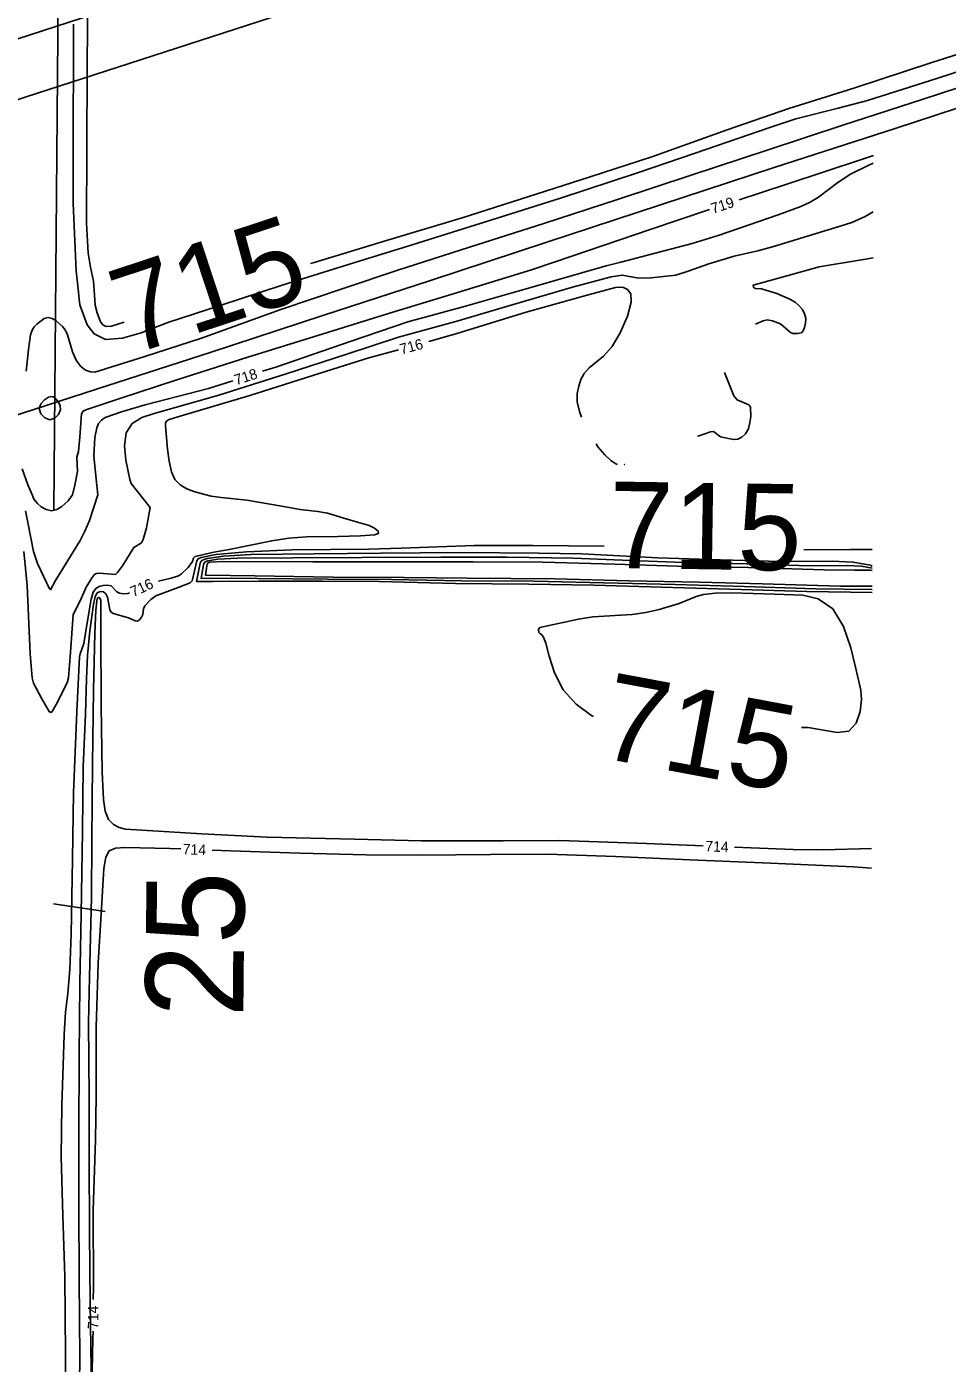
# Model space of a CAD drawing. Extents: x -468556195 to 3353078, y -306091294 to 1252632.
# Drawn here: x 1829727 to 1830079, y 533219 to 533730 of the extents above; entities that cross this region are included whole.
import ezdxf

# ---------------------------------------------------------------- set-up
doc = ezdxf.new("R2010")
doc.units = 0
for name, color, linetype in [('Default', 7, 'Continuous'), ('DT_X_Contour_Minor', 7, 'Continuous'), ('DT_X_Contour_Text', 7, 'Continuous'), ('DT_X_Terrain_Boundary', 7, 'Continuous'), ('Level 14', 7, 'Continuous'), ('Level 19', 7, 'Continuous'), ('SC_Shading3', 7, 'Continuous')]:
    doc.layers.add(name, color=color, linetype=linetype)

msp = doc.modelspace()

# ---------------------------------------------------------------- linework, layer by layer
at = {"layer": 'Default'}
msp.add_lwpolyline([(1827162.83, 532893.73), (1827168.81, 532875.29), (1833162.58, 534815.33), (1833154.87, 534839.74)], close=True, dxfattribs=at)
at = {"layer": 'DT_X_Contour_Minor'}
for points in [[(1829750.3, 533744.67), (1829749.96, 533714.87), (1829749.91, 533683.16), (1829749.77, 533654.89), (1829750.38, 533643.37), (1829751.29, 533638.08), (1829752.41, 533632.77), (1829752.79, 533627.4), (1829753.02, 533623.6), (1829753.83, 533620.59), (1829755.13, 533617.15), (1829755.95, 533616), (1829757.27, 533615.37), (1829759.28, 533615.53), (1829764.14, 533617.13)], [(1830100.23, 533718.38), (1830075.06, 533710.32), (1830048.21, 533701.69), (1830036.99, 533698.75), (1830020.77, 533694.72), (1830010.93, 533691.47), (1829982.37, 533681.62), (1829960.26, 533674.13), (1829930.91, 533664.48), (1829904.6, 533656.1), (1829872.1, 533645.99), (1829854.31, 533640.48), (1829824.46, 533631.2), (1829801.17, 533623.62), (1829780.81, 533616.92), (1829770.68, 533613.04), (1829763.51, 533610.95), (1829757.05, 533610.5), (1829752.62, 533612.57), (1829750, 533616.1), (1829747.14, 533623.66), (1829746.93, 533625.91), (1829746.52, 533629.74), (1829745.83, 533636.55), (1829744.68, 533662.54), (1829744.58, 533667.98), (1829744.69, 533688.03), (1829744.81, 533720.78), (1829744.71, 533730.85)], [(1829835.37, 533639.43), (1829836.33, 533639.72), (1829864.36, 533648.27), (1829893.29, 533656.98), (1829918.44, 533664.94), (1829942.16, 533672.57), (1829965.76, 533680.22), (1829994.55, 533690.55), (1830018.17, 533698.68), (1830032.38, 533703.11), (1830043.4, 533706.57), (1830072.38, 533716.1), (1830100.01, 533724.95), (1830109.68, 533728)], [(1830097.07, 533711.24), (1830069.52, 533702.29), (1830038.82, 533692.35), (1830009.8, 533682.8), (1829980.76, 533673.22), (1829952.6, 533663.98), (1829924.54, 533654.77), (1829896.16, 533645.76), (1829868.71, 533636.95), (1829848.16, 533630.06), (1829823.99, 533621.89), (1829793.65, 533610.93), (1829772.07, 533603.98), (1829752.91, 533597.92), (1829751.24, 533598.07), (1829749.37, 533598.78), (1829747.48, 533600.22), (1829745.78, 533602.53), (1829744.43, 533605.71), (1829742.46, 533612.17), (1829741.57, 533614.17), (1829740.61, 533615.44), (1829738.15, 533617.55), (1829736.65, 533618.49), (1829735.08, 533618.87), (1829733.53, 533618.45), (1829730.8, 533616.34), (1829729.74, 533615.29), (1829728.91, 533614.06), (1829728.29, 533612.24), (1829727.57, 533606.61), (1829726.73, 533598.3)], [(1829999.2, 533663.85), (1830017.39, 533669.84), (1830046.62, 533679.48), (1830050.43, 533680.76)], [(1830050.42, 533677.79), (1830048.65, 533677.07), (1830041.75, 533673.6), (1830036.9, 533670.45), (1830029.42, 533664.81), (1830026.28, 533662.9), (1830022.74, 533661.22), (1830014.08, 533658.03), (1829991.1, 533650.21), (1829981.21, 533647.13), (1829953.98, 533639.94), (1829948.37, 533638.56), (1829919.59, 533630.27), (1829894.54, 533623.23), (1829872.51, 533617.15), (1829850.88, 533609.76), (1829822.14, 533599.92), (1829817.04, 533598.29)], [(1829725.83, 533529.44), (1829727.03, 533516.51), (1829728.15, 533490.43), (1829729.03, 533481.18), (1829729.54, 533479.22), (1829732.7, 533473.2), (1829735.48, 533468.34), (1829736.04, 533468), (1829736.6, 533468.35), (1829738.15, 533471.01), (1829742.36, 533479.26), (1829742.84, 533481.27), (1829743.61, 533490.9), (1829744.68, 533505.39), (1829747.28, 533510.57), (1829749.65, 533515.82), (1829751.84, 533519.49), (1829752.62, 533520.53), (1829753.42, 533521.07), (1829754.59, 533521.2), (1829760.87, 533520.72), (1829761.53, 533521.41), (1829763.51, 533524), (1829767.86, 533531.02), (1829770.71, 533532.83), (1829771.39, 533534.11), (1829772.63, 533538.56), (1829774.1, 533546.29), (1829766.77, 533555.4), (1829766.24, 533556.97), (1829764.82, 533564.31), (1829764.31, 533569.79), (1829764.91, 533574.8), (1829767.21, 533578.32), (1829770.92, 533580.62), (1829775.53, 533582.24), (1829800.33, 533589.16), (1829826.09, 533597.34), (1829849.2, 533604.9), (1829868.94, 533611.3), (1829891.81, 533617.58), (1829910.21, 533623), (1829935.5, 533630.42), (1829950.3, 533634.41), (1829954.51, 533635.05), (1829957.21, 533634.51), (1829960.82, 533633.86), (1829965.55, 533634.06), (1829974.98, 533634.96), (1829979.69, 533636.49), (1829987.61, 533639.29), (1829997.25, 533642.27), (1830006.27, 533644.34), (1830011.94, 533645.82), (1830037.79, 533653.78), (1830042.27, 533655.15), (1830047.35, 533657.48), (1830050.37, 533659.22)], [(1829742.67, 533548.8), (1829744.38, 533551.15), (1829745.32, 533554.8), (1829746.35, 533560.03), (1829746.09, 533565.45), (1829746.62, 533567.62), (1829747.23, 533573.29), (1829747.84, 533582.11), (1829748.43, 533583.07), (1829749.85, 533583.73), (1829762.42, 533587.87), (1829784.27, 533595.01), (1829811.35, 533603.64), (1829840.21, 533612.61), (1829865.11, 533620.32), (1829889.46, 533627.75), (1829919.82, 533637.08), (1829935.58, 533642.38), (1829965.14, 533652.49), (1829987.8, 533660.07)], [(1830050.32, 533641.65), (1830047.42, 533641.08), (1830029.76, 533638.23), (1830017.82, 533634.92), (1830004.49, 533631.19), (1830004.63, 533630.42), (1830005.25, 533629.97), (1830007.71, 533629.83), (1830013.58, 533628.02), (1830018.54, 533625.9), (1830020.51, 533624.68), (1830022.11, 533623.33), (1830023.34, 533621.85), (1830024.17, 533620.24), (1830024.57, 533618.5), (1830024.52, 533616.68), (1830024.14, 533615.01), (1830023.58, 533613.73), (1830022.96, 533613.02), (1830021.48, 533612.68), (1830019.61, 533612.75), (1830018.74, 533613.1), (1830014.9, 533616.43), (1830011.9, 533617.56), (1830009.87, 533617.92), (1830008.37, 533617.6), (1830005.36, 533616.25)], [(1829938.91, 533580.82), (1829938.08, 533582.89), (1829937.27, 533586.67), (1829937.28, 533589.81), (1829937.82, 533592.57), (1829938.69, 533595.12), (1829939.97, 533597.47), (1829941.82, 533599.58), (1829947.32, 533604.02), (1829950.59, 533607.8), (1829953.84, 533613.29), (1829956.5, 533619.4), (1829957.92, 533624.66), (1829957.7, 533627.94), (1829956.44, 533629.57), (1829954.95, 533630.25), (1829953.74, 533630.49), (1829951.9, 533630.25), (1829941.94, 533627.64), (1829917.72, 533620.87), (1829890.9, 533612.56), (1829880.52, 533609.63)], [(1829868.94, 533606.47), (1829857.69, 533603.46), (1829841.5, 533598.36), (1829812.12, 533589.09), (1829785.48, 533581.11), (1829781.27, 533579.84), (1829780.48, 533579.35), (1829779.98, 533578.6), (1829779.86, 533577.42), (1829780.71, 533568.56), (1829781.27, 533564.03), (1829782.17, 533559.93), (1829783.55, 533556.94), (1829785.48, 533554.9), (1829788.04, 533553.45), (1829791.18, 533552.27), (1829797.36, 533550.65), (1829801.14, 533550.04), (1829811.04, 533549.02), (1829823.67, 533546.85), (1829831.38, 533545.56), (1829838.19, 533544.76), (1829841.83, 533544.12), (1829848.11, 533542.26), (1829853.24, 533540.69), (1829857.73, 533539.34), (1829859.79, 533538.34), (1829861.2, 533537.26), (1829861.31, 533536.36), (1829859.75, 533535.8), (1829854.38, 533535.42), (1829845.84, 533535.25), (1829833.92, 533535.12), (1829827.03, 533534.59), (1829820.55, 533533.57), (1829804.28, 533530.17), (1829798.45, 533529.2), (1829791.31, 533527.57), (1829790.64, 533526.94), (1829790.2, 533525.61), (1829788.53, 533523.31), (1829786.03, 533520.92), (1829784.93, 533520.18), (1829782.03, 533519.24), (1829777.3, 533518.1)], [(1829993.56, 533597.83), (1829997.15, 533588.98), (1829998.38, 533587.34), (1830002.88, 533585.53), (1830003.2, 533585.16), (1830003.44, 533584.41), (1830003.55, 533581.07), (1830003.29, 533578.7), (1830002.66, 533576.37), (1830001.59, 533574.46), (1830000.19, 533573.08), (1829998.59, 533572.33), (1829996.94, 533572.21), (1829991.99, 533573.27), (1829989.37, 533575.25), (1829988.14, 533575.19), (1829983.81, 533573.66), (1829983.29, 533573.47)], [(1829805.61, 533594.63), (1829796.36, 533591.67), (1829772.09, 533585.54), (1829763.05, 533582.88), (1829756.85, 533580.7), (1829755.42, 533579.68), (1829754.38, 533578.32), (1829753.68, 533576.68), (1829752.98, 533573.01), (1829752.53, 533565.87), (1829753.73, 533554.65), (1829754.09, 533551.12), (1829750.85, 533541.34), (1829749.15, 533537.2), (1829747.27, 533533.62), (1829737.88, 533518.4), (1829735.94, 533514.85), (1829735.54, 533515.25), (1829730.98, 533524.83), (1829729.45, 533529.5), (1829727.31, 533540.6), (1829726.47, 533544.97)], [(1829737.69, 533588.15), (1829736.99, 533588.61), (1829736.28, 533588.72), (1829735.15, 533588.39), (1829733.62, 533587.41), (1829732.22, 533585.9), (1829731.62, 533584.05), (1829732.27, 533582.1), (1829733.83, 533580.51), (1829735.78, 533579.82), (1829737.63, 533580.37), (1829739.05, 533581.8), (1829739.78, 533583.55), (1829739.65, 533585.17), (1829738.99, 533586.5), (1829737.69, 533588.15)], [(1829952.66, 533562.69), (1829952.04, 533562.94), (1829950.17, 533564.19), (1829947.81, 533566.33), (1829945.14, 533569.5), (1829944.46, 533570.53)], [(1829725.2, 533561.05), (1829727.34, 533554.88), (1829729.11, 533550.87), (1829729.56, 533549.43), (1829731.01, 533547.74), (1829732.47, 533546.55), (1829734.31, 533545.49), (1829736.36, 533545.05), (1829738.4, 533545.53), (1829740.26, 533546.63), (1829742.67, 533548.8)], [(1829955.52, 533562.73), (1829955.35, 533562.64), (1829955.17, 533562.62)], [(1829947.62, 533531.46), (1829920.3, 533531.82), (1829897.82, 533531.71), (1829870.03, 533530.76), (1829857.65, 533530.41), (1829828.38, 533530.08), (1829810.88, 533529.33), (1829799.1, 533528.28), (1829793.51, 533527.13), (1829792.39, 533526.63), (1829791.92, 533525.96), (1829790.09, 533518.27), (1829789.29, 533517.56), (1829784.81, 533515.74), (1829776.26, 533512.56), (1829774.34, 533511.1), (1829772.05, 533508.71), (1829771.57, 533507.59), (1829771.22, 533505.46), (1829770.74, 533504.33), (1829770.03, 533503.36), (1829769.2, 533502.84), (1829768.33, 533502.93), (1829765.77, 533504.12), (1829759.97, 533505.79), (1829759.01, 533506.46), (1829758.6, 533507.36), (1829757.76, 533511.97), (1829757.12, 533513.33), (1829756.25, 533514.04), (1829755.26, 533514.19), (1829754.35, 533513.99), (1829753.63, 533513.5), (1829753.03, 533512.2), (1829752.41, 533509.4), (1829750.99, 533499.16), (1829750.06, 533489.74), (1829749.79, 533480.87), (1829749.33, 533467.38), (1829748.49, 533447.28), (1829748.17, 533422.69), (1829747.73, 533390.92), (1829747.14, 533364.6), (1829746.95, 533336.72), (1829746.74, 533306.74), (1829746.8, 533279.65), (1829746.97, 533251.56), (1829747.24, 533221.66), (1829746.86, 533192.5)], [(1830050.03, 533530.27), (1830041.68, 533530.24), (1830023.88, 533530.08)], [(1830050.01, 533523.78), (1830049.37, 533524.19), (1830042.64, 533525.41), (1830034.66, 533525.73), (1830015.09, 533525.69), (1829992.06, 533526.3), (1829968.02, 533527.03), (1829939.02, 533528.54), (1829922.65, 533528.88), (1829892.64, 533529.12), (1829862.04, 533528.82), (1829836.68, 533528.63), (1829812.7, 533528.33), (1829802.03, 533527.72), (1829795.85, 533526.82), (1829794.3, 533526.31), (1829793.49, 533525.73), (1829793.13, 533524.96), (1829791.8, 533517.98), (1829797.87, 533517.96), (1829815.74, 533518.15), (1829839.95, 533518.1), (1829861.59, 533517.99), (1829890.8, 533517.28), (1829918.83, 533517.03), (1829943.57, 533516.59), (1829973.77, 533515.78), (1829999.87, 533514.93), (1830025, 533514.15), (1830049.99, 533513.87)], [(1830050.01, 533523.12), (1830045.94, 533523.86), (1830040.49, 533524.07), (1830025.89, 533524.03), (1830002.01, 533524.71), (1829974.54, 533525.35), (1829954.62, 533526.18), (1829935.73, 533526.9), (1829910.49, 533527.31), (1829885.19, 533527.31), (1829854.96, 533527.17), (1829828.63, 533527.09), (1829807.38, 533526.96), (1829799.89, 533526.58), (1829796.05, 533525.96), (1829795.09, 533525.48), (1829794.59, 533524.84), (1829794.23, 533523.03), (1829793.52, 533519.2), (1829799.81, 533519.22), (1829814.92, 533519.16), (1829841.99, 533518.88), (1829866.3, 533518.78), (1829893.02, 533518.29), (1829920.86, 533518.08), (1829947.47, 533517.52), (1829974.72, 533516.84), (1830001.02, 533516.13), (1830028.5, 533515.27), (1830049.99, 533515)], [(1830050.01, 533522.17), (1830049.24, 533522.31), (1830043.26, 533522.39), (1830031.62, 533522.51), (1830002.7, 533523.36), (1829975.62, 533523.91), (1829951.67, 533524.68), (1829924.18, 533525.41), (1829897.52, 533525.58), (1829867.37, 533525.53), (1829836.22, 533525.54), (1829802.05, 533525.59), (1829796.86, 533525.33), (1829796.26, 533525.1), (1829795.89, 533524.66), (1829795.59, 533523.1), (1829795.25, 533520.41), (1829814.1, 533520.16), (1829844.03, 533519.67), (1829871.01, 533519.57), (1829895.25, 533519.3), (1829928.68, 533519.03), (1829957.11, 533518.3), (1829983.94, 533517.76), (1830008.01, 533517.13), (1830037.8, 533516.24), (1830049.99, 533516.22)], [(1829766.14, 533513.64), (1829765.47, 533513.41), (1829763.83, 533513.3), (1829762.4, 533513.52), (1829761.31, 533514.06), (1829759.14, 533516.32), (1829757.76, 533516.59), (1829756.11, 533516.51), (1829754.53, 533516.11), (1829753.29, 533515.38), (1829752.34, 533513.9), (1829751.54, 533511.2), (1829750.04, 533502.19), (1829748.65, 533494.32), (1829747.35, 533490.44), (1829747.1, 533489.26), (1829745.98, 533468.41), (1829744.73, 533437.33), (1829744.32, 533411.91), (1829743.84, 533383.23), (1829743.4, 533369.87), (1829742.56, 533360.69), (1829741.75, 533353.54), (1829741.2, 533345), (1829740.26, 533317.87), (1829740.1, 533298.2), (1829740.74, 533275.82), (1829741.43, 533252.58), (1829741.67, 533222.71), (1829741.71, 533200.68)], [(1829985.43, 533416.98), (1829963.78, 533417.87), (1829930.66, 533419.03), (1829909.01, 533418.92), (1829877.71, 533418.95), (1829852.15, 533419.6), (1829818.76, 533420.36), (1829793.86, 533421.59), (1829764.65, 533423.39), (1829762.18, 533424.08), (1829760, 533425.2), (1829758.18, 533427.13), (1829756.87, 533430.25), (1829756.17, 533434.76), (1829755.78, 533445.3), (1829755.3, 533470.6), (1829755.19, 533499.23), (1829755.17, 533510.71), (1829754.89, 533511.7), (1829754.41, 533511.92), (1829753.98, 533511.74), (1829753.66, 533510.67), (1829753.26, 533507.06), (1829752.86, 533498.25), (1829752.46, 533476.47), (1829751.99, 533448.33), (1829751.82, 533419.07), (1829751.58, 533397.37), (1829750.91, 533367.04), (1829750.51, 533349.4), (1829750.73, 533321.04), (1829750.79, 533298.14), (1829750.94, 533269.3), (1829751.18, 533242.54), (1829751.68, 533208.83)], [(1830022.98, 533462.21), (1830025.49, 533462.27), (1830036.66, 533460.33), (1830041.04, 533460.85), (1830043.89, 533463.84), (1830045.39, 533468.34), (1830045.89, 533472.88), (1830045.71, 533476.5), (1830043.66, 533485.24), (1830041.81, 533492.62), (1830039.06, 533500.76), (1830034.96, 533507.53), (1830029.4, 533511.34), (1830023.44, 533512.81), (1830012.78, 533513.21), (1829996.28, 533513.67), (1829989.93, 533513.54), (1829985.54, 533513.02), (1829982.71, 533512.23), (1829976.22, 533509.55), (1829968.55, 533507.35), (1829963.46, 533506.22), (1829958.23, 533505.41), (1829943.25, 533504.53), (1829937.73, 533503.65), (1829923.01, 533500.48), (1829922.46, 533499.73), (1829922.57, 533498.55), (1829922.93, 533498.14), (1829923.5, 533497.89), (1829924.29, 533496.99), (1829925.29, 533494.41), (1829926.56, 533489.5), (1829928.58, 533483.17), (1829931.91, 533476.68), (1829936.87, 533471.11), (1829942.84, 533466.72), (1829943.45, 533466.42)], [(1829752.32, 533243.71), (1829752.36, 533248.37), (1829752.28, 533277.85), (1829753.13, 533304.69), (1829753.42, 533321.36), (1829753.48, 533347.65), (1829754.23, 533372.21), (1829755.36, 533391.05), (1829756.34, 533408.43), (1829757.07, 533412.74), (1829758.42, 533415.18), (1829760.76, 533416.17), (1829764.48, 533416.36), (1829781.56, 533416.02), (1829785.73, 533415.85)], [(1829797.73, 533415.38), (1829804.73, 533415.1), (1829831.32, 533414.23), (1829856.57, 533413.66), (1829877.62, 533413.53), (1829904.11, 533413.79), (1829925.9, 533413.83), (1829951.9, 533412.91), (1829980.28, 533411.64), (1830011.16, 533410.42), (1830042.85, 533409.08), (1830049.71, 533408.47)], [(1830049.73, 533415.98), (1830031.25, 533415.45), (1830019.77, 533415.63), (1829997.42, 533416.49)], [(1829751.64, 533204.27), (1829752.2, 533228.73), (1829752.22, 533231.71)]]:
    msp.add_lwpolyline(points, dxfattribs=at)
at = {"layer": 'DT_X_Contour_Text'}
msp.add_line((1829756.87, 533391.96), (1829737.09, 533394.88), dxfattribs=at)
at = {"layer": 'DT_X_Terrain_Boundary'}
msp.add_line((1829737.27, 533545.36), (1829751.6, 535211.12), dxfattribs=at)
at = {"layer": 'Level 14'}
msp.add_lwpolyline([(1830098.37, 533704.05), (1830058.74, 533691.03), (1830012.54, 533676.09), (1829969.08, 533661.83), (1829925.6, 533647.63), (1829881.16, 533632.98), (1829840.48, 533619.77), (1829797, 533605.52), (1829757.84, 533592.86), (1829696.87, 533573.2), (1829650.56, 533558.13), (1829608.04, 533544.33), (1829564.26, 533529.95), (1829504.85, 533510.57), (1829464.63, 533497.68), (1829417.11, 533482.13), (1829369.91, 533466.93)], dxfattribs=at)
at = {"layer": 'SC_Shading3'}
msp.add_lwpolyline([(1827156.03, 532914.66), (1827168.81, 532875.29), (1833162.58, 534815.33), (1833148.11, 534860.04)], close=True, dxfattribs=at)

# ---------------------------------------------------------------- texts
at = {"layer": 'DT_X_Contour_Text'}
msp.add_text('25', height=37.5, rotation=89.4761, dxfattribs=at).set_placement((1829809.66, 533351.39))
at = {"layer": 'Level 19'}
for s, height, rotation, p in [('719', 4, 18.243, (1829989.13, 533658.42)), ('715', 33, 18.2774, (1829766.34, 533604.27)), ('716', 4, 14.9542, (1829870.08, 533604.7)), ('718', 4, 17.756, (1829806.94, 533592.95)), ('715', 33, 359.1643, (1829949.2, 533523.22)), ('716', 4, 24.8091, (1829767.61, 533512)), ('715', 33, 349.424, (1829944.74, 533450.97)), ('714', 4, 357.7377, (1829786.44, 533413.82)), ('714', 4, 357.6345, (1829986.13, 533414.95)), ('714', 4, 89.5247, (1829754.23, 533232.48))]:
    msp.add_text(s, height=height, rotation=rotation, dxfattribs=at).set_placement(p)

doc.saveas('drawing.dxf')
